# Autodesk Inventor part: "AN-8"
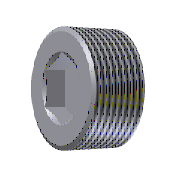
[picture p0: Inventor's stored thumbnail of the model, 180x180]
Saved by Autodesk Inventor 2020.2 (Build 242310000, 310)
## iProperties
Manager: www.cadconsulting.pl
Company: Fabian Stasiak CAD Consulting
Created: 2014-02
Part Number: "AN-8"
Material: Copper,Cu
Description: Pressure plugs
Document SubType Name: Modeling
Designer: F.Stasiak
Standard Revision: 1
Manufacturer: DME
Language: pl-PL
Size Designation: "8"
Categories: <MemberInstance><Categories><Category DisplayName="Forma wtryskowa" InternalName="349578f2-f4d4-4954-8c09-8e99297a61c0" Mnemonic="MOLD"><Category DisplayName="K
Density: 8.96 g/cm^3
Appearance: Aluminium - ciemne
Catalog Web Link: www.expertbooks.pl
IsCustomPart: 1
Author: F.Stasiak
Subject: Zbiór ćwiczeń. Autodesk Inventor 2020. Kurs Professional
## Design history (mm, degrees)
sketch "Sketch1"
  geometry: L1 (0, -3.47)-(0, 20.819) reference; L2 (-2.887, 0)-(-4.864, 0); L3 (-4.864, 0)-(-4.614, 8); L4 (-4.614, 8)-(0, 8); L5 (-12.442, 17.349)-(-12.442, 1.349); L6 (-12.442, 1.349)-(-12.942, 1.349); L7 (-12.942, 1.349)-(-12.442, 17.349); L8 (0, 8)-(0, 3); L9 (-2.887, 0)-(-2.5, 0.223); L10 (-2.5, 0.223)-(-2.5, 3); L11 (-2.5, 3)-(0, 3); 1 further point
  constraints: 20 end point, 3 horizontal, 2 parallel, 2 perpendicular, 1 horizontal alignment, 1 point on line, 1 vertical
  dimensions: "d28" = 8 distance between parallel lines of L2 L4 (= L); "d29" = 9.728 diameter of L2.end L1 (= R_); "d57" = 16 distance of L5.start L5.end (= d100); "d58" = 0.5 distance of L5.end L6.end (= d101); "d62" = 3 distance between parallel lines of L2 L11 (= 0.6 x SW); "d63" = 5 diameter of L10 L1 (= SW); "d64" = 60 deg angle of L10 L9 (= d102); "d65" = 5.7735 diameter of L2.start L1 (= 1.1547 x SW)
revolve "Revolution1" sketch "Sketch1" stored, may be unused: angle "d11" = 90 deg
sketch "Sketch2"
  geometry: L1 (2.887, 0)-(1.443, -2.5); L2 (1.443, -2.5)-(-1.443, -2.5); L3 (-1.443, -2.5)-(-2.887, 0); L4 (-2.887, 0)-(-1.443, 2.5); L5 (-1.443, 2.5)-(1.443, 2.5); L6 (1.443, 2.5)-(2.887, 0); 2 further points
  constraints: 12 end point, 1 coincident, 1 horizontal alignment, 13 other
  dimensions: "d66" = 5 distance between parallel lines of L3 L6 (= SW)
extrude "Extrusion1" cut sketch "Sketch2" distance "d67" = 3 (= 0.6 x SW); taper "d68" = 0 deg
chamfer "Chamfer1" distance "d45" = 0.38685 (= 0.07737 x SW); stored, may be unused: second distance "d46" = 2, angle "d47" = 45 deg
thread "Thread1" dims "d52" = 10, "d53" = 0
body "Solid1"
other parameters: "SW" = 5 [user parameter; used in 6 equation terms], "L" = 8 [user parameter; used in 1 equation term], "d27" = 0, "R_" = 9.728 [user parameter; used in 1 equation term], "d49" = 0, "d61" = 0, "d100" = 16 [user parameter; used in 1 equation term], "d101" = 0.5 [user parameter; used in 1 equation term], "d102" = 60 deg [user parameter; used in 1 equation term]
